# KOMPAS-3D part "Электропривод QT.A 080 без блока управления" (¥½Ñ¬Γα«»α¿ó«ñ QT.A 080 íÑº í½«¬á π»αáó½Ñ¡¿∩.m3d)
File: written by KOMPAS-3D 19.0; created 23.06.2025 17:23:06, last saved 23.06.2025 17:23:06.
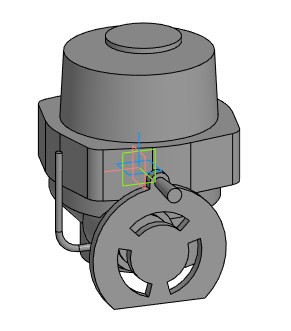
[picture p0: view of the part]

Document properties: Автор: Евгений; Полное имя файла: E:\Dendor Работа Сачек\3D для проектировщиков\3.5 Тип QT.А Электропривод\stp_Электропривод QT.A без блока управления\Электропривод QT.A 080 без блока управления.m3d

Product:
- Part/product: Электропривод QT.A 080 без блока управления

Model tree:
1. Операция без истории:1  (labels: Электропривод QT.A 080 без блока управления)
